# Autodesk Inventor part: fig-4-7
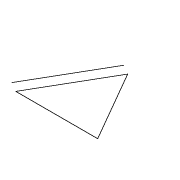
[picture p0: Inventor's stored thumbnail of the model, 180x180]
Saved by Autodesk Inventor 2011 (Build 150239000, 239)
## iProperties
Created: 2005-02
Part Number: fig-4-7
Document SubType Name: Modeling
Designer: CADCIM
Manufacturer: Standard
Standards Organization: Custom
Density: 1 g/cm^3
Author: CADCIM
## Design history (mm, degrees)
sketch "Sketch1"
  geometry: L1 (-3.883, 28.419)-(-24.946, -8.063); L2 (-24.946, -8.063)-(17.18, -8.063); L3 (17.18, -8.063)-(-3.883, 28.419); L4 (-8.847, 31.285)-(-29.909, -5.197)
  constraints: 8 end point, 2 equal length, 1 horizontal, 1 parallel, 1 other
